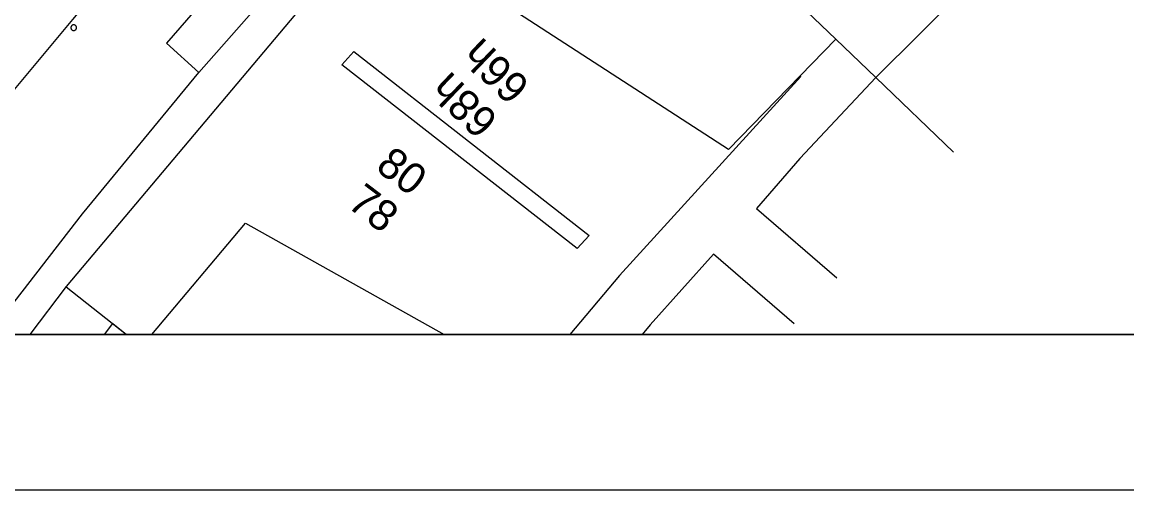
# Model space of a CAD drawing. Extents: x 81065 to 81486, y 452384 to 452681.
# Drawn here: x 81125.76 to 81161.34, y 452383.53 to 452398.58 of the extents above; entities that cross this region are included whole.
import ezdxf

# ---------------------------------------------------------------- set-up
doc = ezdxf.new("R2010")
doc.units = 0
for name, color, linetype in [('B-BH-AL-TOPOGRAFIE_HUISNUMMER-T25', 7, 'Continuous'), ('B-BH-GR-GROENVOORZIENING-GV', 7, 'Continuous'), ('B-BH-IE-MEUBILAIR_WEGMEUBILAIR_PAAL-S', 7, 'Continuous'), ('B-BH-OG-TOPOGRAFIE_BEBOUWING-GV', 7, 'Continuous'), ('B-BH-OG-TOPOGRAFIE_BEBOUWING_PANDSCHEIDING-GV', 7, 'Continuous'), ('B-BH-VH-KANTOPSLUITING-GV', 7, 'Continuous'), ('X-XX-AL-TEKENBLAD_KADER-G', 7, 'Continuous'), ('X-XX-AL-TEKENBLAD_KADER_AFSNIJMARKERING-G', 7, 'Continuous'), ('X-XX-AL-TEKENBLAD_VIEWPORT-G', 7, 'Continuous')]:
    doc.layers.add(name, color=color, linetype=linetype)

msp = doc.modelspace()

# ---------------------------------------------------------------- linework, layer by layer
at = {"layer": 'B-BH-GR-GROENVOORZIENING-GV'}
msp.add_line((81155.756, 452394.391), (81153.251, 452396.796), dxfattribs=at)
at = {"layer": 'B-BH-IE-MEUBILAIR_WEGMEUBILAIR_PAAL-S'}
msp.add_lwpolyline([(81127.332, 452398.398), (81127.333, 452398.388), (81127.334, 452398.379), (81127.337, 452398.369), (81127.34, 452398.36), (81127.344, 452398.352), (81127.35, 452398.344), (81127.356, 452398.336), (81127.362, 452398.33), (81127.37, 452398.324), (81127.378, 452398.318), (81127.387, 452398.314), (81127.395, 452398.311), (81127.405, 452398.308), (81127.414, 452398.307), (81127.424, 452398.306), (81127.433, 452398.307), (81127.443, 452398.308), (81127.452, 452398.311), (81127.461, 452398.314), (81127.47, 452398.318), (81127.478, 452398.324), (81127.485, 452398.33), (81127.492, 452398.336), (81127.498, 452398.344), (81127.503, 452398.352), (81127.507, 452398.36), (81127.511, 452398.369), (81127.513, 452398.379), (81127.515, 452398.388), (81127.515, 452398.398), (81127.515, 452398.407), (81127.513, 452398.417), (81127.511, 452398.426), (81127.507, 452398.435), (81127.503, 452398.443), (81127.498, 452398.451), (81127.492, 452398.459), (81127.485, 452398.466), (81127.478, 452398.472), (81127.47, 452398.477), (81127.461, 452398.481), (81127.452, 452398.485), (81127.443, 452398.487), (81127.433, 452398.489), (81127.424, 452398.489), (81127.414, 452398.489), (81127.405, 452398.487), (81127.395, 452398.485), (81127.387, 452398.481), (81127.378, 452398.477), (81127.37, 452398.472), (81127.362, 452398.466), (81127.356, 452398.459), (81127.35, 452398.451), (81127.344, 452398.443), (81127.34, 452398.435), (81127.337, 452398.426), (81127.334, 452398.417), (81127.333, 452398.407), (81127.332, 452398.398)], dxfattribs=at)
at = {"layer": 'B-BH-OG-TOPOGRAFIE_BEBOUWING-GV'}
for points in [[(81126.018, 452388.532), (81127.195, 452390.075), (81135.264, 452399.653), (81142.254, 452407.263), (81142.332, 452407.331), (81145.191, 452410.261), (81152.12, 452416.954), (81156.495, 452420.925), (81163.982, 452427.288), (81169.073, 452431.334), (81177.002, 452437.212), (81179.582, 452438.967)], [(81153.251, 452396.796), (81151.969, 452398.03), (81148.503, 452394.479), (81139.858, 452400.091), (81144.562, 452405.184), (81143.704, 452406.025), (81150.532, 452412.867), (81157.636, 452419.422), (81158.509, 452420.19), (81166.091, 452426.576), (81171.032, 452430.467), (81180.823, 452437.684), (81181.948, 452438.481)], [(81180.883, 452421.217), (81173.621, 452415.514), (81166.038, 452409.069), (81160.256, 452403.741), (81153.266, 452396.81), (81153.251, 452396.796)], [(81136.443, 452397.628), (81144.02, 452391.715), (81143.638, 452391.29), (81136.061, 452397.203), (81136.443, 452397.628)], [(81150.819, 452396.852), (81150.836, 452396.825), (81145, 452390.432), (81143.396, 452388.532)], [(81129.94, 452388.532), (81132.957, 452392.112), (81139.347, 452388.532)], [(81128.41, 452388.532), (81128.682, 452388.888), (81129.128, 452388.532)]]:
    msp.add_lwpolyline(points, dxfattribs=at)
at = {"layer": 'B-BH-OG-TOPOGRAFIE_BEBOUWING_PANDSCHEIDING-GV'}
for p, q in [((81142.254, 452407.263), (81151.969, 452398.03)), ((81127.184, 452390.061), (81129.121, 452388.532))]:
    msp.add_line(p, q, dxfattribs=at)
at = {"layer": 'B-BH-VH-KANTOPSLUITING-GV'}
for points in [[(81142.75, 452415.423), (81135.885, 452408.332), (81129.439, 452401.115), (81127.389, 452398.664), (81123.349, 452393.832), (81121.926, 452391.977)], [(81133.697, 452401.686), (81130.407, 452397.904), (81131.452, 452396.961)], [(81131.452, 452396.961), (81134.766, 452400.715), (81133.697, 452401.686)], [(81124.69, 452388.532), (81127.703, 452392.408), (81131.452, 452396.961)], [(81153.251, 452396.796), (81150.809, 452394.189), (81149.413, 452392.585)], [(81149.413, 452392.585), (81151.992, 452390.348)], [(81148.027, 452391.108), (81145.988, 452388.838), (81145.731, 452388.532)], [(81150.622, 452388.875), (81148.027, 452391.108)]]:
    msp.add_lwpolyline(points, dxfattribs=at)
at = {"layer": 'X-XX-AL-TEKENBLAD_KADER-G'}
msp.add_lwpolyline([(81480.708, 452388.532), (81070.22, 452388.532), (81070.22, 452675.532), (81480.708, 452675.532)], close=True, dxfattribs=at)
at = {"layer": 'X-XX-AL-TEKENBLAD_KADER_AFSNIJMARKERING-G'}
msp.add_lwpolyline([(81485.714, 452680.532), (81065.214, 452680.532), (81065.214, 452383.532), (81485.714, 452383.532)], close=True, dxfattribs=at)
at = {"layer": 'X-XX-AL-TEKENBLAD_VIEWPORT-G'}
msp.add_lwpolyline([(81070.22, 452388.532), (81480.708, 452388.532), (81480.708, 452675.532), (81070.22, 452675.532)], close=True, dxfattribs=at)

# ---------------------------------------------------------------- texts
at = {"layer": 'B-BH-AL-TOPOGRAFIE_HUISNUMMER-T25'}
for s, rotation, p in [('66h', 136.1728, (81142.165, 452396.585)), ('68h', 136.1728, (81141.143, 452395.486)), ('80', 322.8053, (81137.104, 452393.843)), ('78', 322.8053, (81136.191, 452392.653))]:
    msp.add_text(s, height=1, rotation=rotation, dxfattribs=at).set_placement(p)

doc.saveas('drawing.dxf')
